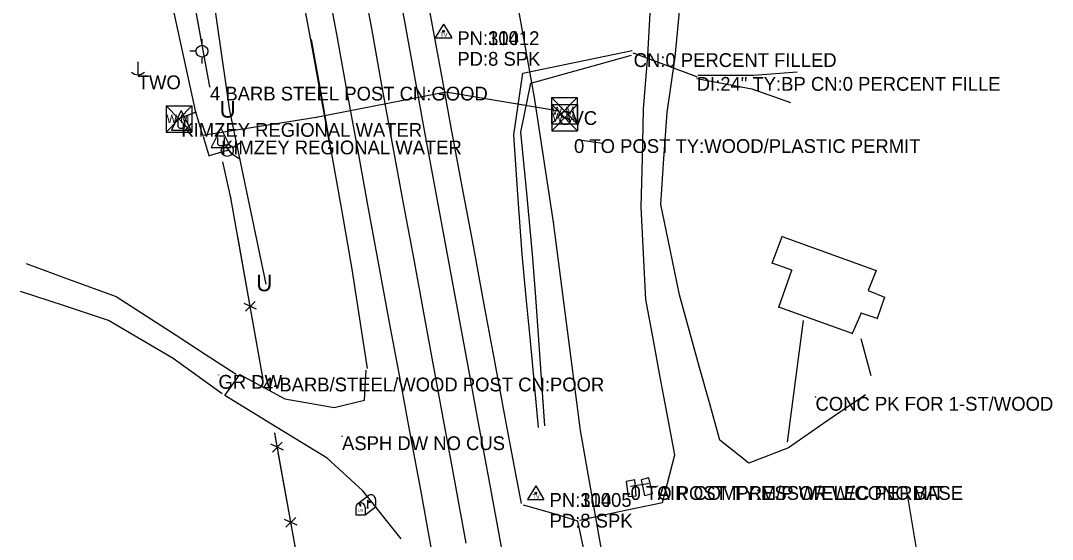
# Model space of a CAD drawing. Extents: x 954793 to 988390, y 1867850 to 1924428.
# Drawn here: x 986021.5 to 986395.5, y 1874357.7 to 1874545.7 of the extents above; entities that cross this region are included whole.
import ezdxf

# ---------------------------------------------------------------- set-up
doc = ezdxf.new("R2010")
doc.units = 0
for name, color, linetype in [('Default', 7, 'Continuous'), ('S_BUILDING', 7, 'Continuous'), ('S_DITCHLINE', 7, 'Continuous'), ('S_DRG_PT_SYM', 7, 'Continuous'), ('S_DRIVEWAY', 7, 'Continuous'), ('S_EDGE_CONCRETE', 7, 'Continuous'), ('S_EDGE_PAVEMENT', 7, 'Continuous'), ('S_FENCE', 7, 'Continuous'), ('S_FENCE_ANNOT', 7, 'Continuous'), ('S_FIBER_OPTIC_CABLE', 7, 'Continuous'), ('S_MAILBOX', 7, 'Continuous'), ('S_MISC_STRUCTURES_ANNOT', 7, 'Continuous'), ('S_MSC_PT_SYM', 7, 'Continuous'), ('S_PAVEMENT_CROWN', 7, 'Continuous'), ('S_SECONDARY_CTL', 7, 'Continuous'), ('S_SECONDARY_CTL_ANNOT', 7, 'Continuous'), ('S_SHOULDER', 7, 'Continuous'), ('S_SIDE_DRAIN', 7, 'Continuous'), ('S_SIDE_DRAIN_ANNOT', 7, 'Continuous'), ('S_SIGN', 7, 'Continuous'), ('S_SIGN_ANNOT', 7, 'Continuous'), ('S_STR_PT_SYM', 7, 'Continuous'), ('S_SURVEY_TEXT_ANNOT', 7, 'Continuous'), ('S_UNDERGROUND_CABLE', 7, 'Continuous'), ('S_UTILITY_POLE', 7, 'Continuous'), ('S_UTILITY_POLE_ANNOT', 7, 'Continuous'), ('S_UTL_PT_SYM', 7, 'Continuous'), ('S_WATER_UTILITIES', 7, 'Continuous'), ('S_WATER_UTILITIES_ANNOT', 7, 'Continuous')]:
    doc.layers.add(name, color=color, linetype=linetype)

msp = doc.modelspace()

# ---------------------------------------------------------------- linework, layer by layer
at = {"layer": 'S_BUILDING'}
for p, q in [((986293.88, 1874457.78), (986297.53, 1874467.45)), ((986297.53, 1874467.45), (986331.59, 1874455.06)), ((986301.04, 1874455.21), (986293.88, 1874457.78)), ((986296.33, 1874441.81), (986301.04, 1874455.21)), ((986331.59, 1874455.06), (986328.77, 1874447.87)), ((986328.77, 1874447.87), (986334.67, 1874445.5)), ((986334.67, 1874445.5), (986332, 1874437.74)), ((986322.94, 1874432.27), (986296.33, 1874441.81)), ((986326.14, 1874439.68), (986322.94, 1874432.27)), ((986332, 1874437.74), (986326.14, 1874439.68))]:
    msp.add_line(p, q, dxfattribs=at)
at = {"layer": 'S_DITCHLINE'}
for points in [[(986209.27, 1874398.26), (986207.77, 1874413.96), (986206.28, 1874429.65), (986204.78, 1874445.35), (986203.29, 1874461.04), (986201.8, 1874482.69), (986200.32, 1874504.34), (986203.6, 1874526.68), (986223.39, 1874530.75), (986243.18, 1874534.82)], [(986211.53, 1874398.84), (986210.42, 1874414.4), (986209.32, 1874429.96), (986208.21, 1874445.51), (986207.1, 1874461.07), (986204.99, 1874483.17), (986202.87, 1874505.26), (986206.48, 1874523.06), (986224.72, 1874528.14), (986242.96, 1874533.22)], [(986302.93, 1874527.03), (986287.17, 1874525.76), (986266.99, 1874525.85)], [(986266.6, 1874524.77), (986286.54, 1874520.96), (986300.57, 1874515.98)]]:
    msp.add_lwpolyline(points, dxfattribs=at)
at = {"layer": 'S_DRG_PT_SYM'}
for points in [[(986243.72, 1874533.88), (986243.72, 1874533.93), (986243.72, 1874533.88), (986243.67, 1874533.88), (986243.72, 1874533.88), (986243.72, 1874533.83), (986243.72, 1874533.88), (986243.77, 1874533.88)], [(986266.58, 1874525.26), (986266.58, 1874525.31), (986266.58, 1874525.26), (986266.53, 1874525.26), (986266.58, 1874525.26), (986266.58, 1874525.21), (986266.58, 1874525.26), (986266.63, 1874525.26)]]:
    msp.add_lwpolyline(points, dxfattribs=at)
at = {"layer": 'S_DRIVEWAY'}
for points in [[(986224.09, 1874364.68), (986239.13, 1874367.86), (986254.17, 1874371.04), (986258.61, 1874388.35), (986255.99, 1874402.4), (986253.37, 1874416.45), (986250.76, 1874430.5), (986248.14, 1874444.55), (986247.31, 1874461.29), (986246.49, 1874478.02), (986246.87, 1874495.81), (986247.25, 1874513.59), (986248.9, 1874533.05), (986249.7, 1874548.44), (986250.51, 1874563.82), (986252.25, 1874578.07), (986254, 1874592.33), (986255.04, 1874604.75), (986256.97, 1874619.55), (986258.9, 1874634.36), (986259.54, 1874649.84), (986260.17, 1874665.31), (986272.49, 1874678.3)], [(986327.7, 1874410.11), (986313.78, 1874400.5), (986299.86, 1874390.9), (986285.43, 1874385.29), (986274.94, 1874393.57), (986271.28, 1874406.76), (986267.61, 1874419.95), (986263.94, 1874433.14), (986260.28, 1874446.33), (986256.91, 1874462.69), (986253.54, 1874479.05), (986254.71, 1874495.75), (986255.88, 1874512.44), (986258.82, 1874532.48), (986260.18, 1874547.78), (986261.53, 1874563.08), (986263.1, 1874576.78), (986264.66, 1874590.48), (986269.75, 1874607.74), (986270.62, 1874620.87), (986271.5, 1874633.99), (986278.96, 1874649.38), (986286.41, 1874664.78)], [(986023.57, 1874457.64), (986039.88, 1874451.67), (986056.2, 1874445.7), (986067.07, 1874438.67), (986077.94, 1874431.64), (986088.81, 1874424.61), (986099.68, 1874417.58)], [(986094.62, 1874410.39), (986076.79, 1874423.18), (986065.06, 1874430.09), (986053.34, 1874436.99), (986037.44, 1874442.28), (986021.54, 1874447.56)], [(986305.14, 1874437), (986302.26, 1874414.97), (986299.39, 1874392.94)], [(986329.82, 1874416.96), (986326.21, 1874430.31)], [(986159.42, 1874357.84), (986145.53, 1874375.26), (986132.64, 1874387.09), (986112.51, 1874399.43), (986095.51, 1874409.77), (986100.96, 1874417.48), (986117.26, 1874408.65), (986135.18, 1874405.42), (986146.19, 1874408.17), (986146.77, 1874419.03)], [(986353.72, 1874310.79), (986350.04, 1874331.85), (986346.29, 1874354.31), (986342.55, 1874376.77)], [(986210.74, 1874329.62), (986223.17, 1874336.54), (986229, 1874338.31), (986226.25, 1874351.26), (986223.51, 1874364.22), (986214.89, 1874366.97), (986203.86, 1874370.04)]]:
    msp.add_lwpolyline(points, dxfattribs=at)
at = {"layer": 'S_EDGE_CONCRETE'}
for points in [[(986244.63, 1874373.47), (986244.1, 1874379.2), (986241.02, 1874378.61), (986241.76, 1874373.22)], [(986250.53, 1874374.32), (986249.28, 1874379.99), (986246.44, 1874379.28), (986247.69, 1874373.61)]]:
    msp.add_lwpolyline(points, close=True, dxfattribs=at)
at = {"layer": 'S_EDGE_PAVEMENT'}
for points in [[(986170.43, 1874354.1), (986166.53, 1874375.62), (986162.86, 1874395.4), (986159.19, 1874415.19), (986155.25, 1874436.26), (986151.31, 1874457.33), (986147.52, 1874478.23), (986143.73, 1874499.13), (986139.92, 1874519.94), (986136.1, 1874540.75), (986132.06, 1874562.52), (986128.02, 1874584.3), (986123.99, 1874606.27), (986119.96, 1874628.24), (986116.07, 1874649.54), (986112.18, 1874670.84), (986108.25, 1874692.44), (986104.33, 1874714.04), (986100.38, 1874736.09), (986096.43, 1874758.13), (986092.68, 1874779.05)], [(986199.31, 1874335.79), (986195.2, 1874358.19), (986191.08, 1874380.6), (986187.39, 1874400.55), (986183.7, 1874420.5), (986179.85, 1874441.38), (986176, 1874462.27), (986172.02, 1874483.76), (986168.04, 1874505.24), (986164.39, 1874525.3), (986160.74, 1874545.35), (986156.75, 1874566.92), (986152.77, 1874588.5), (986148.73, 1874610.58), (986144.7, 1874632.66), (986140.79, 1874653.96), (986136.89, 1874675.26), (986132.94, 1874696.99), (986129, 1874718.71), (986125.01, 1874740.74), (986121.02, 1874762.76)]]:
    msp.add_lwpolyline(points, dxfattribs=at)
at = {"layer": 'S_FENCE'}
for p, q in [((986090.17, 1874521.74), (986076.6, 1874595.67)), ((986097.78, 1874481.5), (986094.8, 1874494.52)), ((986109.36, 1874416.29), (986097.78, 1874481.5)), ((986107.04, 1874441.09), (986102.5, 1874443.2)), ((986103, 1874440.38), (986106.54, 1874443.92)), ((986124.15, 1874337.99), (986113.63, 1874396.11)), ((986116.81, 1874390.03), (986112.27, 1874392.12)), ((986112.78, 1874389.3), (986116.3, 1874392.85)), ((986121.75, 1874362.78), (986117.2, 1874364.87)), ((986117.72, 1874362.05), (986121.23, 1874365.6))]:
    msp.add_line(p, q, dxfattribs=at)
for points in [[(986090.17, 1874521.74), (986085.79, 1874545.6)], [(986104.52, 1874443.56), (986100.28, 1874467.45)], [(986109.36, 1874416.29), (986105.12, 1874440.18)], [(986114.29, 1874392.49), (986113.63, 1874396.11)], [(986119.22, 1874365.24), (986114.9, 1874389.11)], [(986124.15, 1874337.99), (986119.83, 1874361.86)]]:
    msp.add_lwpolyline(points, dxfattribs=at)
at = {"layer": 'S_FIBER_OPTIC_CABLE'}
for p, q in [((986207.82, 1874517.82), (986192.94, 1874600.02)), ((986214.72, 1874472.69), (986207.82, 1874517.82)), ((986224.49, 1874397.12), (986214.72, 1874472.69)), ((986236.59, 1874328.39), (986224.49, 1874397.12))]:
    msp.add_line(p, q, dxfattribs=at)
at = {"layer": 'S_MAILBOX'}
for p, q in [((986143.63, 1874370.53), (986147.76, 1874373.64)), ((986147.25, 1874371.82), (986147.25, 1874369.1)), ((986150.2, 1874372.16), (986150.2, 1874369.45)), ((986143.08, 1874369.26), (986143.08, 1874366.54)), ((986146.4, 1874366.54), (986150.2, 1874369.45)), ((986146.4, 1874369.26), (986146.4, 1874366.54)), ((986143.08, 1874366.54), (986146.4, 1874366.54))]:
    msp.add_line(p, q, dxfattribs=at)
for points in [[(986147.25, 1874371.82), (986148.35, 1874371.15), (986147.25, 1874370.81)], [(986144.26, 1874370.37), (986144.48, 1874370.23), (986144.48, 1874369.84), (986144.79, 1874369.84), (986144.79, 1874370.2), (986144.59, 1874370.45), (986144.26, 1874370.4)]]:
    msp.add_lwpolyline(points, dxfattribs=at)
for centre, end in [((986148.53, 1874372.16), 117.5718), ((986144.74, 1874369.26), 180)]:
    msp.add_arc(centre, 1.66, 0, end, dxfattribs=at)
msp.add_ellipse((986147.25, 1874369.1), major_axis=(0.145, 0.132), ratio=0.564646, dxfattribs=at)
at = {"layer": 'S_MSC_PT_SYM'}
for points in [[(986090.17, 1874521.74), (986090.17, 1874521.79), (986090.17, 1874521.74), (986090.12, 1874521.74), (986090.17, 1874521.74), (986090.17, 1874521.69), (986090.17, 1874521.74), (986090.22, 1874521.74)], [(986232.41, 1874501.25), (986232.41, 1874501.3), (986232.41, 1874501.25), (986232.36, 1874501.25), (986232.41, 1874501.25), (986232.41, 1874501.2), (986232.41, 1874501.25), (986232.46, 1874501.25)], [(986097.78, 1874481.5), (986097.78, 1874481.55), (986097.78, 1874481.5), (986097.73, 1874481.5), (986097.78, 1874481.5), (986097.78, 1874481.45), (986097.78, 1874481.5), (986097.83, 1874481.5)], [(986093.25, 1874417.25), (986093.25, 1874417.3), (986093.25, 1874417.25), (986093.2, 1874417.25), (986093.25, 1874417.25), (986093.25, 1874417.2), (986093.25, 1874417.25), (986093.3, 1874417.25)], [(986109.36, 1874416.29), (986109.36, 1874416.34), (986109.36, 1874416.29), (986109.31, 1874416.29), (986109.36, 1874416.29), (986109.36, 1874416.24), (986109.36, 1874416.29), (986109.41, 1874416.29)], [(986309.62, 1874409.3), (986309.62, 1874409.35), (986309.62, 1874409.3), (986309.57, 1874409.3), (986309.62, 1874409.3), (986309.62, 1874409.25), (986309.62, 1874409.3), (986309.67, 1874409.3)], [(986113.63, 1874396.11), (986113.63, 1874396.16), (986113.63, 1874396.11), (986113.58, 1874396.11), (986113.63, 1874396.11), (986113.63, 1874396.06), (986113.63, 1874396.11), (986113.68, 1874396.11)], [(986138.03, 1874395.02), (986138.03, 1874395.07), (986138.03, 1874395.02), (986137.98, 1874395.02), (986138.03, 1874395.02), (986138.03, 1874394.97), (986138.03, 1874395.02), (986138.08, 1874395.02)], [(986242.6, 1874376.95), (986242.6, 1874377), (986242.6, 1874376.95), (986242.55, 1874376.95), (986242.6, 1874376.95), (986242.6, 1874376.9), (986242.6, 1874376.95), (986242.65, 1874376.95)], [(986248.94, 1874377.89), (986248.94, 1874377.94), (986248.94, 1874377.89), (986248.89, 1874377.89), (986248.94, 1874377.89), (986248.94, 1874377.84), (986248.94, 1874377.89), (986248.99, 1874377.89)], [(986252.39, 1874376.97), (986252.39, 1874377.02), (986252.39, 1874376.97), (986252.34, 1874376.97), (986252.39, 1874376.97), (986252.39, 1874376.92), (986252.39, 1874376.97), (986252.44, 1874376.97)]]:
    msp.add_lwpolyline(points, dxfattribs=at)
at = {"layer": 'S_PAVEMENT_CROWN'}
msp.add_lwpolyline([(986183, 1874356.29), (986179.03, 1874378.2), (986175.3, 1874398.49), (986171.57, 1874418.77), (986167.81, 1874439.23), (986164.05, 1874459.68), (986160.12, 1874480.72), (986156.19, 1874501.75), (986152.5, 1874522.28), (986148.81, 1874542.82), (986144.75, 1874564.76), (986140.69, 1874586.7), (986136.65, 1874608.69), (986132.6, 1874630.68), (986128.76, 1874652.02), (986124.92, 1874673.35), (986121.01, 1874694.86), (986117.1, 1874716.36), (986113.07, 1874738.52), (986109.04, 1874760.67)], dxfattribs=at)
at = {"layer": 'S_SECONDARY_CTL'}
for p, q in [((986174.82, 1874544.45), (986171.81, 1874539.5)), ((986174.82, 1874544.45), (986177.77, 1874539.5)), ((986171.81, 1874539.5), (986177.77, 1874539.5)), ((986208.24, 1874377.06), (986205.23, 1874372.11)), ((986208.24, 1874377.06), (986211.19, 1874372.11)), ((986205.23, 1874372.11), (986211.19, 1874372.11))]:
    msp.add_line(p, q, dxfattribs=at)
for centre, radius in [((986174.82, 1874541.84), 0.311), ((986174.82, 1874541.84), 0.183), ((986174.82, 1874541.84), 0.103), ((986208.24, 1874374.45), 0.311), ((986208.24, 1874374.45), 0.183), ((986208.24, 1874374.45), 0.103)]:
    msp.add_circle(centre, radius, dxfattribs=at)
at = {"layer": 'S_SHOULDER'}
for points in [[(986147.31, 1874419.63), (986144.49, 1874437.61), (986141.67, 1874455.59), (986138.02, 1874476.5), (986134.37, 1874497.42), (986130.63, 1874518.12), (986126.88, 1874538.82), (986130.56, 1874518.09), (986134.25, 1874497.36), (986130.51, 1874518.03), (986126.77, 1874538.7), (986122.64, 1874560.72), (986118.51, 1874582.75), (986114.56, 1874604.7), (986110.62, 1874626.64), (986106.77, 1874647.78), (986102.92, 1874668.92), (986098.87, 1874690.54), (986094.81, 1874712.15), (986090.8, 1874734.33), (986086.78, 1874756.51), (986082.99, 1874777.27)], [(986203.06, 1874370.69), (986200.88, 1874382.05), (986197.2, 1874401.78), (986193.53, 1874421.5), (986189.57, 1874442.78), (986185.62, 1874464.06), (986181.6, 1874485.51), (986177.59, 1874506.95), (986173.93, 1874527.05), (986170.26, 1874547.15), (986166.19, 1874568.84), (986162.13, 1874590.53), (986158.1, 1874612.35), (986154.07, 1874634.18), (986150.23, 1874655.68), (986146.39, 1874677.19), (986142.5, 1874699.01), (986138.6, 1874720.82), (986134.67, 1874742.6), (986130.73, 1874764.39)]]:
    msp.add_lwpolyline(points, dxfattribs=at)
at = {"layer": 'S_SIDE_DRAIN'}
msp.add_line((986266.58, 1874525.26), (986243.72, 1874533.88), dxfattribs=at)
at = {"layer": 'S_SIGN'}
for p, q in [((986224.07, 1874502.44), (986232.41, 1874501.25)), ((986242.6, 1874376.95), (986248.94, 1874377.89))]:
    msp.add_line(p, q, dxfattribs=at)
at = {"layer": 'S_STR_PT_SYM'}
for points in [[(986297.53, 1874467.45), (986297.53, 1874467.5), (986297.53, 1874467.45), (986297.48, 1874467.45), (986297.53, 1874467.45), (986297.53, 1874467.4), (986297.53, 1874467.45), (986297.58, 1874467.45)], [(986293.88, 1874457.78), (986293.88, 1874457.83), (986293.88, 1874457.78), (986293.83, 1874457.78), (986293.88, 1874457.78), (986293.88, 1874457.73), (986293.88, 1874457.78), (986293.93, 1874457.78)], [(986301.04, 1874455.21), (986301.04, 1874455.26), (986301.04, 1874455.21), (986300.99, 1874455.21), (986301.04, 1874455.21), (986301.04, 1874455.16), (986301.04, 1874455.21), (986301.09, 1874455.21)], [(986331.59, 1874455.06), (986331.59, 1874455.11), (986331.59, 1874455.06), (986331.54, 1874455.06), (986331.59, 1874455.06), (986331.59, 1874455.01), (986331.59, 1874455.06), (986331.64, 1874455.06)], [(986328.77, 1874447.87), (986328.77, 1874447.92), (986328.77, 1874447.87), (986328.72, 1874447.87), (986328.77, 1874447.87), (986328.77, 1874447.82), (986328.77, 1874447.87), (986328.82, 1874447.87)], [(986334.67, 1874445.5), (986334.67, 1874445.55), (986334.67, 1874445.5), (986334.62, 1874445.5), (986334.67, 1874445.5), (986334.67, 1874445.45), (986334.67, 1874445.5), (986334.72, 1874445.5)], [(986296.33, 1874441.81), (986296.33, 1874441.86), (986296.33, 1874441.81), (986296.28, 1874441.81), (986296.33, 1874441.81), (986296.33, 1874441.76), (986296.33, 1874441.81), (986296.38, 1874441.81)], [(986326.14, 1874439.68), (986326.14, 1874439.73), (986326.14, 1874439.68), (986326.09, 1874439.68), (986326.14, 1874439.68), (986326.14, 1874439.63), (986326.14, 1874439.68), (986326.19, 1874439.68)], [(986332, 1874437.74), (986332, 1874437.79), (986332, 1874437.74), (986331.95, 1874437.74), (986332, 1874437.74), (986332, 1874437.69), (986332, 1874437.74), (986332.05, 1874437.74)], [(986322.94, 1874432.27), (986322.94, 1874432.32), (986322.94, 1874432.27), (986322.89, 1874432.27), (986322.94, 1874432.27), (986322.94, 1874432.22), (986322.94, 1874432.27), (986322.99, 1874432.27)]]:
    msp.add_lwpolyline(points, dxfattribs=at)
at = {"layer": 'S_UNDERGROUND_CABLE'}
for p, q in [((986097.31, 1874513.07), (986090.2, 1874563.28)), ((986079.78, 1874513.1), (986076.25, 1874506.01)), ((986079.78, 1874513.1), (986083.27, 1874506.01)), ((986110.59, 1874450.13), (986097.31, 1874513.07)), ((986078.58, 1874507.25), (986078.58, 1874509.69)), ((986079.2, 1874506.59), (986078.58, 1874507.25)), ((986080.4, 1874506.59), (986079.2, 1874506.59)), ((986080.94, 1874507.25), (986080.4, 1874506.59)), ((986080.94, 1874509.69), (986080.94, 1874507.25)), ((986094.16, 1874506.77), (986090.64, 1874499.68)), ((986094.16, 1874506.77), (986097.65, 1874499.68)), ((986076.25, 1874506.01), (986083.27, 1874506.01)), ((986092.96, 1874500.92), (986092.96, 1874503.36)), ((986095.33, 1874503.36), (986095.33, 1874500.92)), ((986090.64, 1874499.68), (986097.65, 1874499.68)), ((986093.58, 1874500.26), (986092.96, 1874500.92)), ((986094.78, 1874500.26), (986093.58, 1874500.26)), ((986095.33, 1874500.92), (986094.78, 1874500.26))]:
    msp.add_line(p, q, dxfattribs=at)
at = {"layer": 'S_UTILITY_POLE'}
for p, q in [((986087.28, 1874536.72), (986087.28, 1874538.97)), ((986085.18, 1874534.59), (986082.86, 1874534.59)), ((986087.35, 1874530.17), (986087.35, 1874532.5)), ((986063.97, 1874530.78), (986063.97, 1874526.05))]:
    msp.add_line(p, q, dxfattribs=at)
msp.add_circle((986087.28, 1874534.61), 2.13, dxfattribs=at)
msp.add_arc((986064.03, 1874529.47), 3.41, 226.3972, 313.6028, dxfattribs=at)
at = {"layer": 'S_UTL_PT_SYM'}
for points in [[(986175.62, 1874519.81), (986175.62, 1874519.86), (986175.62, 1874519.81), (986175.57, 1874519.81), (986175.62, 1874519.81), (986175.62, 1874519.76), (986175.62, 1874519.81), (986175.67, 1874519.81)], [(986207.82, 1874517.82), (986207.82, 1874517.87), (986207.82, 1874517.82), (986207.77, 1874517.82), (986207.82, 1874517.82), (986207.82, 1874517.77), (986207.82, 1874517.82), (986207.87, 1874517.82)], [(986079.62, 1874510.37), (986079.62, 1874510.42), (986079.62, 1874510.37), (986079.57, 1874510.37), (986079.62, 1874510.37), (986079.62, 1874510.32), (986079.62, 1874510.37), (986079.67, 1874510.37)], [(986084.73, 1874512.35), (986084.73, 1874512.4), (986084.73, 1874512.35), (986084.68, 1874512.35), (986084.73, 1874512.35), (986084.73, 1874512.3), (986084.73, 1874512.35), (986084.78, 1874512.35)], [(986085.08, 1874512.46), (986085.08, 1874512.51), (986085.08, 1874512.46), (986085.03, 1874512.46), (986085.08, 1874512.46), (986085.08, 1874512.41), (986085.08, 1874512.46), (986085.13, 1874512.46)], [(986128.65, 1874510.52), (986128.65, 1874510.57), (986128.65, 1874510.52), (986128.6, 1874510.52), (986128.65, 1874510.52), (986128.65, 1874510.47), (986128.65, 1874510.52), (986128.7, 1874510.52)], [(986216.74, 1874512.88), (986216.74, 1874512.93), (986216.74, 1874512.88), (986216.69, 1874512.88), (986216.74, 1874512.88), (986216.74, 1874512.83), (986216.74, 1874512.88), (986216.79, 1874512.88)], [(986087.62, 1874504.05), (986087.62, 1874504.1), (986087.62, 1874504.05), (986087.57, 1874504.05), (986087.62, 1874504.05), (986087.62, 1874504), (986087.62, 1874504.05), (986087.67, 1874504.05)], [(986087.88, 1874503.53), (986087.88, 1874503.58), (986087.88, 1874503.53), (986087.83, 1874503.53), (986087.88, 1874503.53), (986087.88, 1874503.48), (986087.88, 1874503.53), (986087.93, 1874503.53)], [(986089.82, 1874496.74), (986089.82, 1874496.79), (986089.82, 1874496.74), (986089.77, 1874496.74), (986089.82, 1874496.74), (986089.82, 1874496.69), (986089.82, 1874496.74), (986089.87, 1874496.74)], [(986096.43, 1874498.63), (986096.43, 1874498.68), (986096.43, 1874498.63), (986096.38, 1874498.63), (986096.43, 1874498.63), (986096.43, 1874498.58), (986096.43, 1874498.63), (986096.48, 1874498.63)], [(986214.72, 1874472.69), (986214.72, 1874472.74), (986214.72, 1874472.69), (986214.67, 1874472.69), (986214.72, 1874472.69), (986214.72, 1874472.64), (986214.72, 1874472.69), (986214.77, 1874472.69)], [(986224.49, 1874397.12), (986224.49, 1874397.17), (986224.49, 1874397.12), (986224.44, 1874397.12), (986224.49, 1874397.12), (986224.49, 1874397.07), (986224.49, 1874397.12), (986224.54, 1874397.12)]]:
    msp.add_lwpolyline(points, dxfattribs=at)
at = {"layer": 'S_WATER_UTILITIES'}
for p, q in [((986085.08, 1874512.46), (986068.18, 1874590.34)), ((986175.62, 1874519.81), (986128.65, 1874510.52)), ((986216.74, 1874512.88), (986175.62, 1874519.81)), ((986213.9, 1874517.78), (986223.24, 1874517.78)), ((986213.9, 1874517.78), (986213.9, 1874508.29)), ((986213.9, 1874517.78), (986223.24, 1874508.29)), ((986223.24, 1874517.78), (986213.9, 1874508.29)), ((986223.24, 1874517.78), (986223.24, 1874508.29)), ((986074.24, 1874514.78), (986083.58, 1874514.78)), ((986074.24, 1874514.78), (986074.24, 1874505.29)), ((986074.24, 1874514.78), (986083.58, 1874505.29)), ((986083.58, 1874514.78), (986074.24, 1874505.29)), ((986083.58, 1874514.78), (986083.58, 1874505.29)), ((986214.07, 1874515.28), (986223.41, 1874515.28)), ((986214.07, 1874515.28), (986214.07, 1874505.79)), ((986214.07, 1874515.28), (986223.41, 1874505.79)), ((986223.41, 1874515.28), (986214.07, 1874505.79)), ((986223.41, 1874515.28), (986223.41, 1874505.79)), ((986084.73, 1874512.35), (986079.62, 1874510.37)), ((986087.62, 1874504.05), (986085.08, 1874512.46)), ((986128.65, 1874510.52), (986087.62, 1874504.05)), ((986213.9, 1874508.29), (986223.24, 1874508.29)), ((986074.24, 1874505.29), (986083.58, 1874505.29)), ((986089.82, 1874496.74), (986087.88, 1874503.53)), ((986214.07, 1874505.79), (986223.41, 1874505.79)), ((986098.34, 1874499.69), (986101.16, 1874501.42)), ((986096.43, 1874498.63), (986089.82, 1874496.74)), ((986098.21, 1874497.38), (986101.12, 1874495.46))]:
    msp.add_line(p, q, dxfattribs=at)
msp.add_circle((986096.43, 1874498.64), 2.18, dxfattribs=at)

# ---------------------------------------------------------------- texts
at = {"layer": 'Default'}
for p in [(986093.68, 1874510.52), (986106.96, 1874447.59)]:
    msp.add_text('U', height=6, rotation=360, dxfattribs=at).set_placement(p)
at = {"layer": 'S_FENCE_ANNOT'}
for s, p in [('4 BARB STEEL POST CN:GOOD', (986090.17, 1874516.74)), ('4-BARB/STEEL/WOOD POST CN:POOR', (986109.36, 1874411.29))]:
    msp.add_text(s, height=5, dxfattribs=at).set_placement(p)
at = {"layer": 'S_MAILBOX'}
msp.add_text('US', height=0.96, rotation=360, dxfattribs=at).set_placement((986143.84, 1874367.73))
at = {"layer": 'S_MISC_STRUCTURES_ANNOT'}
msp.add_text('AIR COMPRESSOR W/CONC BASE', height=5, dxfattribs=at).set_placement((986252.39, 1874371.97))
at = {"layer": 'S_SECONDARY_CTL'}
for p in [(986173.62, 1874539.83), (986207.03, 1874372.44)]:
    msp.add_text('TV', height=1.5, rotation=360, dxfattribs=at).set_placement(p)
at = {"layer": 'S_SECONDARY_CTL_ANNOT'}
for s, p in [('PN:30012', (986179.82, 1874536.84)), ('PN:1141', (986179.82, 1874536.84)), ('PD:8 SPK', (986179.82, 1874529.34)), ('PD:8 SPK', (986179.82, 1874529.34)), ('PN:1140', (986213.24, 1874369.45)), ('PN:30005', (986213.24, 1874369.45)), ('PD:8 SPK', (986213.24, 1874361.95)), ('PD:8 SPK', (986213.24, 1874361.95))]:
    msp.add_text(s, height=5, dxfattribs=at).set_placement(p)
at = {"layer": 'S_SIDE_DRAIN_ANNOT'}
for s, p in [('CN:0 PERCENT FILLED', (986243.72, 1874528.88)), ('DI:24" TY:BP CN:0 PERCENT FILLE', (986266.58, 1874520.26))]:
    msp.add_text(s, height=5, dxfattribs=at).set_placement(p)
at = {"layer": 'S_SIGN_ANNOT'}
for s, p in [('0 TO POST TY:WOOD/PLASTIC PERMIT', (986222.11, 1874497.72)), ('0 TO POST TY:M/P W/ELEC PERMIT', (986242.6, 1874371.95))]:
    msp.add_text(s, height=5, dxfattribs=at).set_placement(p)
at = {"layer": 'S_SURVEY_TEXT_ANNOT'}
for s, p in [('GR DW', (986093.25, 1874412.25)), ('CONC PK FOR 1-ST/WOOD', (986309.62, 1874404.3)), ('ASPH DW NO CUS', (986138.03, 1874390.02))]:
    msp.add_text(s, height=5, dxfattribs=at).set_placement(p)
at = {"layer": 'S_UTILITY_POLE_ANNOT'}
for s, p in [('TWO', (986063.99, 1874520.83)), ('KIMZEY REGIONAL WATER', (986079.78, 1874503.57)), ('KIMZEY REGIONAL WATER', (986094.16, 1874497.23))]:
    msp.add_text(s, height=5, dxfattribs=at).set_placement(p)
at = {"layer": 'S_WATER_UTILITIES'}
for p in [(986214.11, 1874511.55), (986074.44, 1874508.55), (986214.28, 1874509.05)]:
    msp.add_text('W M', height=3, rotation=360, dxfattribs=at).set_placement(p)
at = {"layer": 'S_WATER_UTILITIES_ANNOT'}
msp.add_text('SVC', height=5, dxfattribs=at).set_placement((986216.74, 1874507.88))

doc.saveas('drawing.dxf')
